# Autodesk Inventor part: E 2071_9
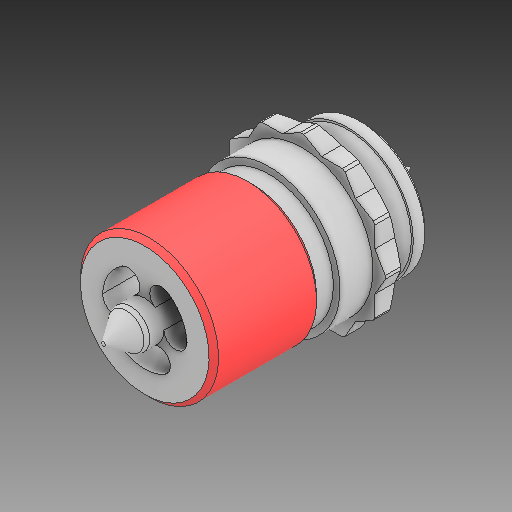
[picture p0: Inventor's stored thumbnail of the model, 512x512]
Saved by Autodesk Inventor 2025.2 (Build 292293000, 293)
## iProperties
Created: 2025-04
Part Number: E 2071_9
Material: Všeobecné
Document SubType Name: Modeling
Designer: Patrik
Density: 1 g/cm^3
Appearance: Výchozí
Mass: 5.6725 g
Surface Area: 41.677 cm^2
Volume: 5.6725 cm^3
Author: Patrik
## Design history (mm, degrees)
feature "Base1"
node "Těleso1"
